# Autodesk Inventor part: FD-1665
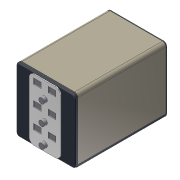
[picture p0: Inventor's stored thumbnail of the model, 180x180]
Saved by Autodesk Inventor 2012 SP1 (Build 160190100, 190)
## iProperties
Created: 2012-03
Part Number: FD-1665
Material: Wood (Cherry)
Document SubType Name: Modeling
Designer: jdh
Density: 0.5 g/cm^3
Mass: 590.211 g
Surface Area: 708.044 cm^2
Volume: 1180.42 cm^3
Author: jdh
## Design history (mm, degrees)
sketch "Sketch1"
  geometry: L1 (-44.45, 97.028)-(44.45, 97.028); L2 (44.45, 97.028)-(44.45, 5.08); L3 (44.45, 5.08)-(-44.45, 5.08); L4 (-44.45, 5.08)-(-44.45, 97.028); L5 (0, 0)-(0, 27.098)
  constraints: 10 end point, 3 parallel, 1 horizontal, 1 perpendicular, 1 other
  dimensions: "d0" = 97.028 distance from line of L1 L5.start; "d1" = 88.9 distance of L1.start L1.end; "d3" = 5.08 distance from line of L3 L5.start
extrude "Extrusion1" new body sketch "Sketch1" distance "d4" = 132.08; taper "d5" = 0 deg
fillet "Fillet2" dims "d7" = 5.08
fillet "Fillet3" dims "d8" = 0.127
sketch "Sketch4"
  geometry: L1 (-44.45, 91.948)-(-44.45, 5.207) reference; L2 (-44.323, 5.08)-(44.323, 5.08) reference; L3 (44.45, 5.207)-(44.45, 91.948) reference; L4 (-44.45, 5.08)-(44.45, 5.08); L5 (44.45, 5.08)-(44.45, 3.81); L6 (40.64, 0)-(-40.64, 0); L7 (-44.45, 3.81)-(-44.45, 5.08); A1 r 3.81 centre (-40.64, 3.81) between (-44.45, 3.81) and (-40.64, 0); A2 r 3.81 centre (40.64, 3.81) between (40.64, 0) and (44.45, 3.81); 1 further point
  constraints: 8 end point, 4 point on circle, 4 tangent, 3 collinear, 2 centre point, 2 parallel, 1 equal radius, 1 horizontal, 1 midpoint, 1 perpendicular
  dimensions: "d11" = 3.81 radius of A1
extrude "Extrusion3" join sketch "Sketch4" stored distance "d12" = 0; taper "d13" = 0 deg
fillet "Fillet4" dims "d14" = 0.127
sketch "Sketch5"
  geometry: L1 (39.37, 97.028)-(-39.37, 97.028) reference; L2 (-44.45, 91.948)-(-44.45, 5.207) reference; L3 (44.45, 5.207)-(44.45, 91.948) reference; L4 (44.45, 3.81)-(44.45, 4.953) reference; L5 (-40.64, 0)-(40.64, 0) reference; L6 (-44.45, 4.953)-(-44.45, 3.81) reference; L7 (-44.45, 5.207)-(-44.45, 4.953); L8 (44.45, 5.207)-(44.45, 4.953); A1 r 5.08 centre (-39.37, 91.948) between (-39.37, 97.028) and (-44.45, 91.948) reference; A2 r 5.08 centre (39.37, 91.948) between (44.45, 91.948) and (39.37, 97.028) reference; A3 r 3.81 centre (40.64, 3.81) between (40.64, 0) and (44.45, 3.81) reference; A4 r 3.81 centre (-40.64, 3.81) between (-44.45, 3.81) and (-40.64, 0) reference; 1 further point
  constraints: 4 end point, 1 collinear, 1 parallel
extrude "Extrusion4" join sketch "Sketch5" distance "d15" = 2.032; taper "d16" = 0 deg
fillet "Fillet5" dims "d17" = 1.016
sketch "Sketch6"
  geometry: L1 (-40.64, 0)-(40.64, 0) reference; L2 (-44.45, 91.948)-(-44.45, 5.207) reference; L3 (39.37, 97.028)-(-39.37, 97.028) reference; L4 (44.45, 5.207)-(44.45, 91.948) reference; L5 (-39.37, 0.381)-(39.37, 0.381); L6 (-39.37, 5.461)-(-44.45, 5.461); L7 (-39.37, 5.461)-(-39.37, 0.381); L8 (39.37, 5.461)-(44.45, 5.461); L9 (39.37, 5.461)-(39.37, 0.381); A1 r 5.08 centre (39.37, 91.948) between (44.45, 91.948) and (39.37, 97.028) reference; A2 r 5.08 centre (-39.37, 91.948) between (-39.37, 97.028) and (-44.45, 91.948) reference; A3 r 5.08 centre (-39.37, 5.461) between (-44.45, 5.461) and (-39.37, 0.381); A4 r 5.08 centre (39.37, 5.461) between (39.37, 0.381) and (44.45, 5.461); 1 further point
  constraints: 10 end point, 4 point on circle, 2 centre point, 2 point on line, 2 vertical, 1 parallel
  dimensions: "d18" = 0.381 distance between parallel lines of L5 L1; "d19" = 5.08 radius of A3; "d20" = 90 deg angle of L6 L7; "d21" = 5.08 radius of A4; "d22" = 90 deg angle of L9 L8
extrude "Extrusion5" join sketch "Sketch6" distance "d23" = 4.064; taper "d24" = 0 deg
chamfer "Chamfer1" distance "d25" = 1.524; stored, may be unused: second distance "d26" = 3.175, angle "d27" = 45 deg
sketch "Sketch7"
  geometry: L1 (39.37, 97.028)-(-39.37, 97.028) reference; L2 (-44.45, 91.948)-(-44.45, 5.461) reference; L3 (44.45, 5.461)-(44.45, 91.948) reference; L4 (-39.37, 0.381)-(39.37, 0.381) reference; L5 (-15.875, 94.945)-(15.875, 94.945); L6 (23.495, 87.325)-(23.495, 10.084); L7 (15.875, 2.464)-(-15.875, 2.464); L8 (-23.495, 10.084)-(-23.495, 87.325); A1 r 7.62 centre (-15.875, 87.325) between (-15.875, 94.945) and (-23.495, 87.325); A2 r 7.62 centre (15.875, 87.325) between (23.495, 87.325) and (15.875, 94.945); A3 r 7.62 centre (15.875, 10.084) between (15.875, 2.464) and (23.495, 10.084); A4 r 7.62 centre (-15.875, 10.084) between (-23.495, 10.084) and (-15.875, 2.464); 1 further point
  constraints: 8 end point, 8 point on circle, 8 tangent, 4 centre point, 3 equal radius, 2 parallel, 1 horizontal, 1 perpendicular
  dimensions: "d28" = 20.955 distance between parallel lines of L3 L6; "d29" = 20.955 distance between parallel lines of L8 L2; "d30" = 2.0828 distance between parallel lines of L1 L5; "d31" = 2.0828 distance between parallel lines of L4 L7; "d32" = 7.62 radius of A1
extrude "Extrusion6" join sketch "Sketch7" distance "d33" = 1.27; taper "d34" = 0 deg
sketch "Sketch8"
  geometry: L1 (-23.495, 10.084)-(-23.495, 87.325) reference; L2 (15.875, 2.464)-(-15.875, 2.464) reference; L3 (23.495, 87.325)-(23.495, 10.084) reference; L4 (16.739, 22.403)-(5.232, 22.403); L5 (5.232, 22.403)-(5.232, 30.785); L6 (5.232, 30.785)-(16.739, 30.785); L7 (16.739, 30.785)-(16.739, 22.403); L8 (-5.232, 22.403)-(-16.739, 22.403); L9 (-16.739, 22.403)-(-16.739, 30.785); L10 (-16.739, 30.785)-(-5.232, 30.785); L11 (-5.232, 30.785)-(-5.232, 22.403); L12 (16.739, 51.994)-(5.232, 51.994); L13 (5.232, 51.994)-(5.232, 60.376); L14 (5.232, 60.376)-(16.739, 60.376); L15 (16.739, 60.376)-(16.739, 51.994); L16 (-5.232, 51.994)-(-16.739, 51.994); L17 (-16.739, 51.994)-(-16.739, 60.376); L18 (-16.739, 60.376)-(-5.232, 60.376); L19 (-5.232, 60.376)-(-5.232, 51.994); L20 (16.739, 81.585)-(5.232, 81.585); L21 (5.232, 81.585)-(5.232, 89.967); L22 (5.232, 89.967)-(16.739, 89.967); L23 (16.739, 89.967)-(16.739, 81.585); L24 (-5.232, 81.585)-(-16.739, 81.585); L25 (-16.739, 81.585)-(-16.739, 89.967); L26 (-16.739, 89.967)-(-5.232, 89.967); L27 (-5.232, 89.967)-(-5.232, 81.585); 1 further point
  constraints: 48 end point, 14 collinear, 12 parallel, 6 horizontal, 6 perpendicular
  dimensions: "d35" = 6.7564 distance between parallel lines of L7 L3; "d36" = 6.7564 distance between parallel lines of L1 L9; "d37" = 11.5062 distance between parallel lines of L5 L7; "d38" = 11.5062 distance between parallel lines of L9 L11; "d39" = 8.382 distance between parallel lines of L6 L4; "d40" = 8.382 distance between parallel lines of L14 L12; "d41" = 8.382 distance between parallel lines of L22 L20; "d42" = 19.939 distance between parallel lines of L2 L4; "d54" = 29.591 distance between parallel lines of L12 L4; "d55" = 29.591 distance between parallel lines of L20 L12
extrude "Extrusion7" cut sketch "Sketch8" stored distance "d45" = 49.53 (= d43); taper "d46" = 0 deg
sketch "Sketch9"
  geometry: L1 (15.875, 2.464)-(-15.875, 2.464) reference; L2 (-15.875, 94.945)-(15.875, 94.945) reference; L3 (0, 2.464)-(0, 94.945); C1 r 4.128 at (0, 11.887); C2 r 4.128 at (0, 41.351); C3 r 4.128 at (0, 70.815); 1 further point
  constraints: 3 centre point, 3 point on line, 2 end point, 2 equal radius, 2 midpoint
  dimensions: "d47" = 9.4234 distance from line of L1 C1.centre; "d48" = 8.255 diameter of C1; "d50" = 29.464 distance of C1.centre C2.centre; "d51" = 29.464 distance of C2.centre C3.centre
extrude "Extrusion8" join sketch "Sketch9" distance "d52" = 4.826; taper "d53" = 0 deg
sketch "Sketch10"
  geometry: L1 (0, -2.159)-(81.28, -2.159) reference; L2 (40.64, 170.967)-(40.64, -31.013) reference; 5 further points
  constraints: 5 point on line
  dimensions: "d56" = 48.26 distance from line of L1 point (40.64, 46.101); "d57" = 34.036 distance from line of L1 point (40.64, 31.877); "d58" = 22.86 distance from line of point (40.64, 20.701) L1; "d59" = 73.66 distance from line of point (40.64, 71.501) L1; "d100" = 99.06 distance from line of L1 point (40.64, 96.901)
hole "Hole1" sketch "Sketch10" diameter "d60" = 4.9784; stored, may be unused: countersink angle "d64" = 82 deg, drill point angle "d66" = 118 deg; dims "d61" = 8.89, "d62" = 9.525, "d63" = 6.35, "d65" = 11.43
hole "Hole2" sketch "Sketch10" diameter "d67" = 4.9276; stored, may be unused: countersink angle "d71" = 82 deg, drill point angle "d73" = 118 deg; dims "d68" = 8.89, "d69" = 9.525, "d70" = 6.35, "d72" = 11.43
sketch "Sketch11"
  geometry: L1 (32.528, 28.092)-(-30.383, 28.092); L2 (-40.64, 0)-(40.64, 0) reference; L3 (0, 0)-(0, 56.198); C1 r 28.105 at (0, 56.198); C2 r 22.009 at (0, 56.198)
  constraints: 4 end point, 2 centre point, 2 coincident, 1 perpendicular, 1 tangent
  dimensions: "d74" = 56.2102 diameter of C1; "d75" = 28.0924 distance between parallel lines of L2 L1; "d76" = 6.096 radial gap between concentric circles of C1 C2
extrude "Extrusion9" join sketch "Sketch11" distance "d77" = 1.27; taper "d78" = 0 deg
sketch "Sketch12"
  geometry: C1 r 22.009 at (0, 0) reference; C2 r 28.105 at (0, 0) reference; C3 r 23.432 at (0, 0); 1 further point
  constraints: 1 centre point, 1 coincident
  dimensions: "d80" = 4.6736 radial gap between concentric circles of C2 C3
extrude "Extrusion10" cut sketch "Sketch12" distance "d81" = 1.143; taper "d82" = 0 deg
sketch "Sketch13"
  geometry: C1 r 22.009 at (0, 0) reference; 1 further point
extrude "Extrusion11" cut sketch "Sketch13" distance "d83" = 3.937; taper "d84" = 0 deg
sketch "Sketch14"
  geometry: L1 (0, 0)-(0, 23.432); L2 (0, 0)-(20.292, 11.716); L3 (0, 0)-(20.292, -11.716); L4 (0, 0)-(0, -23.432); L5 (0, 0)-(-20.292, -11.716); L6 (0, 0)-(-20.292, 11.716); A1 r 23.432 centre (0, 0) between (0, 23.432) and (20.292, 11.716) reference; 1 further point
  constraints: 12 end point, 6 point on circle, 1 vertical
  dimensions: "d85" = 60 deg angle of L2 L1; "d86" = 60 deg angle of L3 L2; "d87" = 60 deg angle of L3 L4; "d88" = 60 deg angle of L4 L5; "d89" = 60 deg angle of L5 L6
extrude "Extrusion12" cut sketch "Sketch14" distance "d90" = 3.937; taper "d91" = 0 deg
sketch "Sketch15"
  geometry: C1 r 22.009 at (0, 0) reference; 1 further point
extrude "Extrusion13" cut sketch "Sketch15" distance "d92" = 9.3218; taper "d93" = 0 deg
sketch "Sketch16"
  geometry: C1 r 22.009 at (0, 0) reference; C2 r 11.659 at (0, 0); 1 further point
  constraints: 1 centre point, 1 coincident
  dimensions: "d94" = 23.3172 diameter of C2
extrude "Extrusion14" cut sketch "Sketch16" distance "d95" = 2.921; taper "d96" = 0 deg
chamfer "Chamfer2" distance "d97" = 1.27; stored, may be unused: second distance "d98" = 3.175, angle "d99" = 45 deg
body "Solid1"
node "Projected Loop1"
other parameters: "d43" = 49.53
